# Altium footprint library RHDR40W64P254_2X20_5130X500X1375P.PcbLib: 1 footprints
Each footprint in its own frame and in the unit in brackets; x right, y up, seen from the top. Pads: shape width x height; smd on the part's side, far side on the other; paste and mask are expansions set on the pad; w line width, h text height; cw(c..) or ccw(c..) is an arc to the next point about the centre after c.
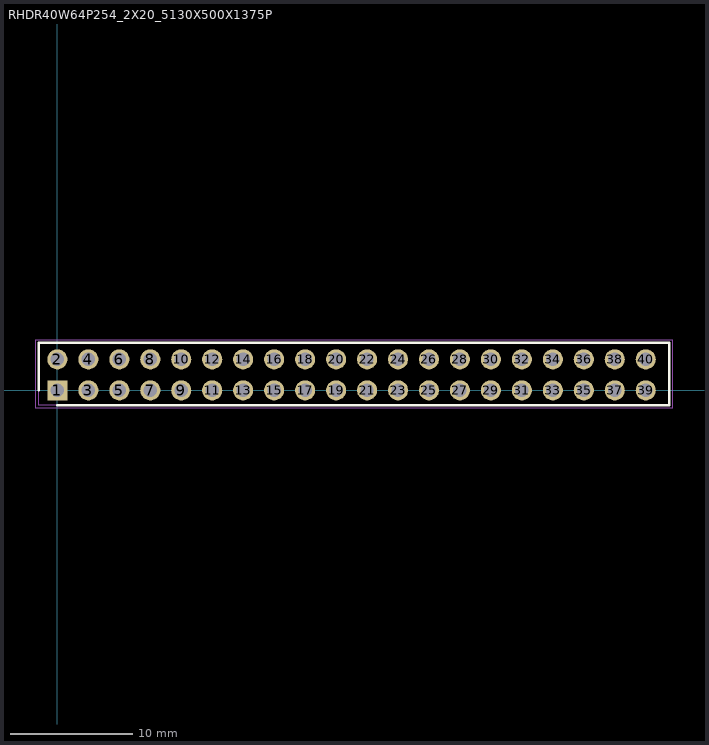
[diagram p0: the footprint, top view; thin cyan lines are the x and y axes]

## RHDR40W64P254_2X20_5130X500X1375P [mm]
pads (40):
  rect 1.65x1.65 / inner round 1.65 / far side rect 1.65x1.65 hole 1.1: 1(0,0)
  round 1.65 hole 1.1: 2(0,2.54) 3(2.54,0) 4(2.54,2.54) 5(5.08,0) 6(5.08,2.54) 7(7.62,0) 8(7.62,2.54) 9(10.16,0) 10(10.16,2.54) 11(12.7,0) 12(12.7,2.54) 13(15.24,0) 14(15.24,2.54) 15(17.78,0) 16(17.78,2.54) 17(20.32,0) 18(20.32,2.54) 19(22.86,0) 20(22.86,2.54) 21(25.4,0) 22(25.4,2.54) 23(27.94,0) 24(27.94,2.54) 25(30.48,0) 26(30.48,2.54) 27(33.02,0) 28(33.02,2.54) 29(35.56,0) 30(35.56,2.54) 31(38.1,0) 32(38.1,2.54) 33(40.64,0) 34(40.64,2.54) 35(43.18,0) 36(43.18,2.54) 37(45.72,0) 38(45.72,2.54) 39(48.26,0) 40(48.26,2.54)
Top Overlay:
  lines w0.2: -1.52,0 -1.52,3.92 50.18,3.92 50.18,-1.23 0,-1.23
Mechanical 15:
  lines w0.1: -1.52,-1.23 -1.52,3.92 50.18,3.92 50.18,-1.23 -1.52,-1.23
Mechanical 20:
  lines w0.05: -1.77,-1.48 -1.77,4.17 50.43,4.17 50.43,-1.48 -1.77,-1.48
